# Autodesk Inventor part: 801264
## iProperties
Created: 2007-11
Part Number: 801264
Document SubType Name: Modeling
Designer: TH
Density: 7.85 g/cm^3
Mass: 31.545 g
Surface Area: 19.7101 cm^2
Volume: 4.01847 cm^3
Material: Steel
Description: R23423 - M12 x 16
Component Category: Fasteners
Author: TH
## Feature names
1. Extrusion1
2. Revolution1
3. Revolution2
4. Fillet1
